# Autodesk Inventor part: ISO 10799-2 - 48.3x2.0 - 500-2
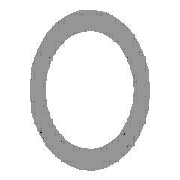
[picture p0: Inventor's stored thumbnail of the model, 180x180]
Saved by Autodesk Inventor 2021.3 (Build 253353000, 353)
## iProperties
_CCFamilyMember: 14
_CCFamilyDisplayName: ISO 10799-2 (Profils creux circulaires - Formés à froid) - Aciers de construction - Coupes creuses profilées formées à froid, soudées
_FrameMemberDoc: Frame Member File
_Version: 25.0.0
_GetPNFromCC: 1
IsCustomPart: 1
Created: 2018-07
Part Number: ISO 10799-2 - 48.3x2.0 - 500-2
Material: Acier, doux
Description: Aciers de construction - Coupes creuses profilées formées à froid, soudées
Document SubType Name: Modeling
Standard: ISO
Designer: Fabian Perrée
Standard Revision: First edition 2011-09-15
Standards Organization: ISO
Language: fr-FR
Size Designation: 48.3x2.0
Categories: <MemberInstance><Categories><Category DisplayName="Profilés" InternalName="089c4875-fa83-4c05-b084-43b9cc11f5ed" Mnemonic="GRDR"><CategoryParameter DisplayName=
Stock Number: 48.3x2.0
Density: 7.85 g/cm^3
Appearance: Semi-poli
Mass: 1103.72 g
Surface Area: 1414.8 cm^2
Volume: 140.601 cm^3
G_L: 500,000 mm
G_W: 48,300 mm
G_H: 48,300 mm
+827D7E4F-AC72-4F13-A4D1-31AC1668D8DC+DETAILDECOUPE1: Grugeage
Author: Fabian Perrée
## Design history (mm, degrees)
node "Plan de départ"
node "Plan de fin"
sketch "Esquisse"
  geometry: C1 r 22.15 at (0, 0); C2 r 24.15 at (0, 0); 2 further points
  constraints: 3 coincident, 2 centre point
  dimensions: "d0" = 48.3 diameter of C2 (= G_H); "d1" = 2 radial gap between concentric circles of C2 C1 (= G_T)
extrude "Corps" new body sketch "Esquisse" stored distance "d2" = 500 (= G_L); taper "d3" = 0 deg
node "Driven Length"
  sketch "Sketch3"
    geometry: L1 (0, 0)-(10, 0) reference
    constraints: 2 end point, 1 horizontal
  workplane "Work Plane3"
  sketch "Sketch4"
    geometry: L1 (-2, 0)-(12, 0) reference; L2 (-2, 500)-(12, 500) reference
    dimensions: "d7" = 500 distance between parallel lines of L1 L2 (derived)
body "Solid1"
feature "Sculpter1"
feature "Combiner1"
body "Srf14"
body "Srf15"
node "Solide6"
feature "Surface1"
body "Srf13"
feature "Carreau délimité9" dims "d24" = 5, "d25" = 0
feature "Carreau délimité10" dims "d26" = 5, "d27" = 0
other parameters: "G_H" = 48.3 [user parameter; used in 1 equation term], "G_T" = 2 [user parameter; used in 1 equation term], "G_L" = 500 (= d7) [user parameter; used in 1 equation term], "G_OFFSET_START" = 0 [user parameter; used in 1 equation term], "G_OFFSET_END" = 0 [user parameter; used in 1 equation term], "d4" = 0 (computed from G_OFFSET_START), "d5" = 500 (= G_OFFSET_END + B_L), "B_L" = 500 [user parameter; used in 1 equation term], "d6" = 90 deg, "MAS" = 0.228 [user parameter]
